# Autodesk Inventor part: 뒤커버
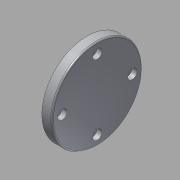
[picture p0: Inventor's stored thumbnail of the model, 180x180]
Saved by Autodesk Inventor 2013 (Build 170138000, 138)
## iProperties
Created: 2015-09
Part Number: 뒤커버
Material: 알루미늄 6061
Document SubType Name: Modeling
Designer: mduedu
Density: 1 g/cm^3
Author: mduedu
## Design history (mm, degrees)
sketch "스케치1"
  geometry: L1 (-15.5, 47)-(-15.5, 78); L2 (-15.5, 78)-(-22.5, 78); L3 (-22.5, 78)-(-22.5, 67); L4 (-25.5, 67)-(-25.5, 47); L5 (-79.5, 39.5)-(-79.5, 54.5) reference; L6 (48.5, 54.5)-(48.5, 39.5) reference; L7 (-79.5, 47)-(48.5, 47); L8 (-22.5, 67)-(-25.5, 67); L9 (-25.5, 47)-(-15.5, 47); 1 further point
  constraints: 14 end point, 4 midpoint, 3 parallel, 1 collinear, 1 point on line, 1 vertical
  dimensions: "d6" = 62 diameter of L2 L7; "d7" = 7 distance of L1.end L2.end; "d8" = 40 diameter of L3.end L7; "d32" = 10 distance between parallel lines of L1 L4
revolve "회전1" sketch "스케치1" stored, may be unused: angle "d4" = 90 deg
sketch "스케치4"
  geometry: C1 r 31 at (0, 0) reference; 2 further points
  constraints: 1 coincident
hole "구멍3" sketch "스케치4" at (0, 0) diameter "d33" = 33; stored, may be unused: countersink angle "d37" = 90 deg, drill point angle "d39" = 0 deg; dims "d34" = 6, "d35" = 4, "d36" = 2, "d38" = 5
fillet "모깎기4" dims "d40" = 1
chamfer "모따기2" distance "d41" = 1; stored, may be unused: second distance "d42" = 2, angle "d43" = 45 deg
sketch "스케치5" dims "d44" = 48
  geometry: C1 r 31 at (0, 0) reference; 6 further points
  constraints: 2 vertical alignment, 1 coincident, 7 other
  dimensions: "d47" = 360 deg dimension on C1.centre point (0, -24) (derived)
sketch "스케치6"
  geometry: 4 further points
hole "구멍4" sketch "스케치6" at (24, 0), (0, 24), (-24, 0), (0, -24) diameter "d49" = 3.4; stored, may be unused: countersink angle "d53" = 90 deg, drill point angle "d55" = 0 deg; dims "d50" = 6, "d51" = 6.5, "d52" = 3.4, "d54" = 8
node "솔리드1"
node "참조1"
node "참조2"
